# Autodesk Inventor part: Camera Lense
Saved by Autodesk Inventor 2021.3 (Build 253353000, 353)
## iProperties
Created: 2023-02
Part Number: Camera Lense
Material: Generic
Document SubType Name: Modeling
Designer: AdminForWorker
Density: 1 g/cm^3
Appearance: Default
Title: Camera Lense
Author: AdminForWorker
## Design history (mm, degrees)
feature "Camera Lense"
feature "Lense Glass"
body "Solid1"
body "Solid2"
